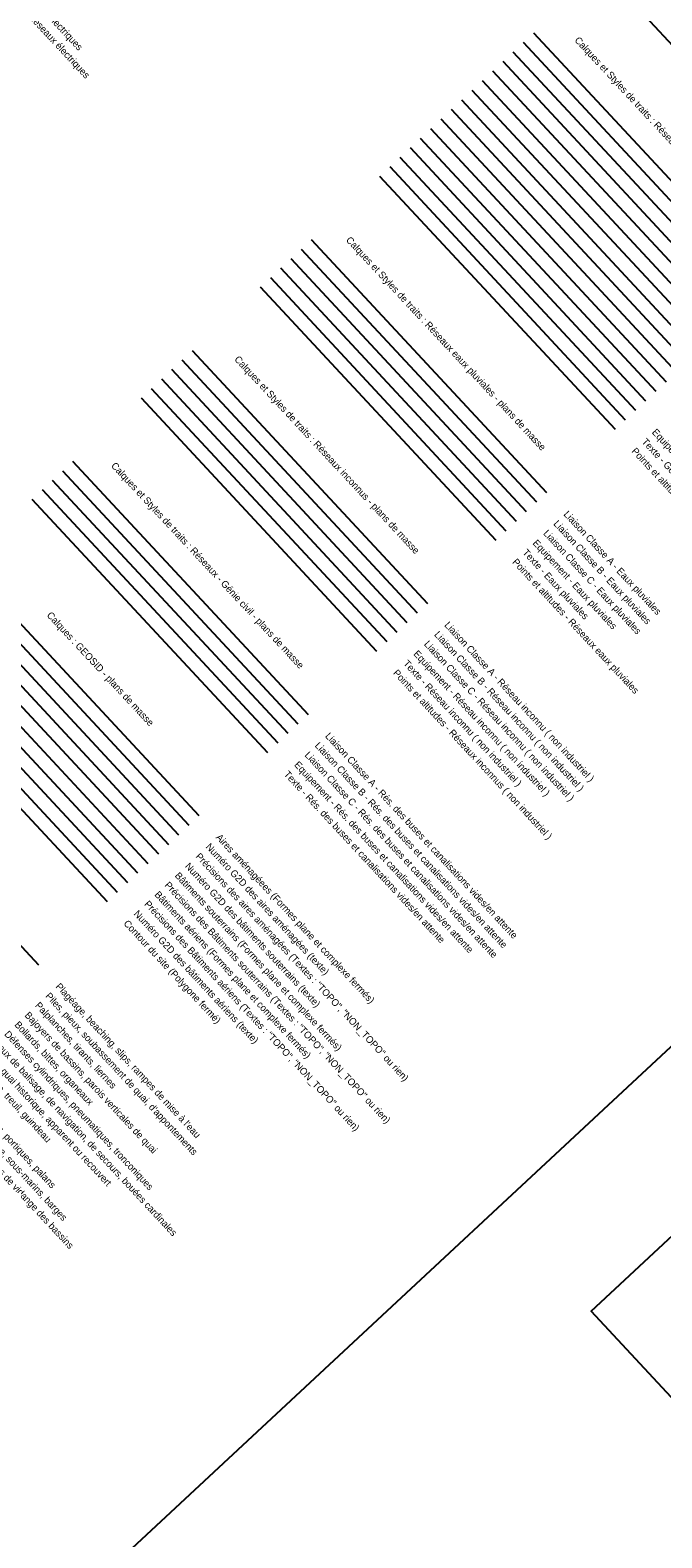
# Model space of a CAD drawing. Extents: x 704383 to 706615, y 7057567 to 7059313.
# Drawn here: x 706453 to 706498.3, y 7057621.5 to 7057729.7 of the extents above; entities that cross this region are included whole.
import ezdxf

# ---------------------------------------------------------------- set-up
doc = ezdxf.new("R2010")
doc.units = 0
for name, color, linetype in [('DH_CADRE -CARTOUCHE', 7, 'Continuous'), ('GEOSID_AIRE_AMENAGEE_NUMERO', 7, 'Continuous'), ('GEOSID_AIRE_AMENAGEE_POLYGONE', 7, 'Continuous'), ('GEOSID_AIRE_AMENAGEE_PRECISION', 7, 'Continuous'), ('GEOSID_BATI_AERIEN _POLYGONE', 7, 'Continuous'), ('GEOSID_BATI_AERIEN_NUMERO', 7, 'Continuous'), ('GEOSID_BATI_AERIEN_PRECISION', 7, 'Continuous'), ('GEOSID_BATI_SOUTERRAIN_NUMERO', 7, 'Continuous'), ('GEOSID_BATI_SOUTERRAIN_POLYGONE', 7, 'Continuous'), ('GEOSID_BATI_SOUTERRAIN_PRECISION', 7, 'Continuous'), ('GEOSID_SITE_POLYGONE', 7, 'Continuous'), ('OM_BAJOYER', 7, 'Continuous'), ('OM_BOLLARDS', 7, 'Continuous'), ('OM_CABESTAN', 7, 'Continuous'), ('OM_DEFENSE D ACCOSTAGE', 7, 'Continuous'), ('OM_EQUIP DE LEVAGE', 7, 'Continuous'), ('OM_GALERIE REFOULEMENT', 7, 'Continuous'), ('OM_NAVIRE', 7, 'Continuous'), ('OM_PAL TIR LIER', 7, 'Continuous'), ('OM_PLAGEAGE', 7, 'Continuous'), ('OM_QUAI', 7, 'Continuous'), ('OM_SIGNAL NAUTIQUE', 7, 'Continuous'), ('OM_SOUBASSEMENT', 7, 'Continuous'), ('R_CF_ALT_POINT', 7, 'Continuous'), ('R_CH_ALT_POINT', 7, 'Continuous'), ('R_CH_GEOTHERMIE_CANALISATION_CL_A', 7, 'Continuous'), ('R_CH_GEOTHERMIE_CANALISATION_CL_B', 7, 'Continuous'), ('R_CH_GEOTHERMIE_CANALISATION_CL_C', 7, 'Continuous'), ('R_CH_GEOTHERMIE_EQUIP', 7, 'Continuous'), ('R_CH_GEOTHERMIE_TEXTE', 7, 'Continuous'), ('R_CH_PRIM_CANALISATION_CL_A', 7, 'Continuous'), ('R_CH_PRIM_CANALISATION_CL_B', 7, 'Continuous'), ('R_CH_PRIM_CANALISATION_CL_C', 7, 'Continuous'), ('R_CH_PRIM_EQUIP', 7, 'Continuous'), ('R_CH_PRIM_TEXTE', 7, 'Continuous'), ('R_CH_SECOND_CANALISATION_CL_A', 7, 'Continuous'), ('R_CH_SECOND_CANALISATION_CL_B', 7, 'Continuous'), ('R_CH_SECOND_CANALISATION_CL_C', 7, 'Continuous'), ('R_CH_SECOND_EQUIP', 7, 'Continuous'), ('R_CH_SECOND_TEXTE', 7, 'Continuous'), ('R_ELEC_ALT_POINT', 7, 'Continuous'), ('R_ELEC_POSTE', 7, 'Continuous'), ('R_GC_BUSES_CANA_CL_A', 7, 'Continuous'), ('R_GC_BUSES_CANA_CL_B', 7, 'Continuous'), ('R_GC_BUSES_CANA_CL_C', 7, 'Continuous'), ('R_GC_BUSES_CANA_EQUIP', 7, 'Continuous'), ('R_GC_BUSES_CANA_TEXTE', 7, 'Continuous'), ('R_INCONNU_ALT_POINT', 7, 'Continuous'), ('R_INCONNU_CANALISATION_CL_A', 7, 'Continuous'), ('R_INCONNU_CANALISATION_CL_B', 7, 'Continuous'), ('R_INCONNU_CANALISATION_CL_C', 7, 'Continuous'), ('R_INCONNU_EQUIP', 7, 'Continuous'), ('R_INCONNU_TEXTE', 7, 'Continuous'), ('R_PLU_ALT_POINT', 7, 'Continuous'), ('R_PLU_CANALISATION_CL_A', 7, 'Continuous'), ('R_PLU_CANALISATION_CL_B', 7, 'Continuous'), ('R_PLU_CANALISATION_CL_C', 7, 'Continuous'), ('R_PLU_EQUIP', 7, 'Continuous'), ('R_PLU_TEXTE', 7, 'Continuous')]:
    doc.layers.add(name, color=color, linetype=linetype)

msp = doc.modelspace()

# ---------------------------------------------------------------- linework, layer by layer
at = {"layer": 'DH_CADRE -CARTOUCHE'}
for points in [[(706481.84, 7057811.55), (706566.98, 7057720.03), (706402.25, 7057566.77), (706317.1, 7057658.29)], [(706573.79, 7057712.71), (706614.66, 7057668.78), (706534.12, 7057593.85), (706493.26, 7057637.78)]]:
    msp.add_lwpolyline(points, close=True, dxfattribs=at)
at = {"layer": 'GEOSID_AIRE_AMENAGEE_NUMERO'}
msp.add_line((706447.47, 7057690.82), (706464.37, 7057672.66), dxfattribs=at)
at = {"layer": 'GEOSID_AIRE_AMENAGEE_POLYGONE'}
msp.add_line((706448.2, 7057691.5), (706465.1, 7057673.34), dxfattribs=at)
at = {"layer": 'GEOSID_AIRE_AMENAGEE_PRECISION'}
msp.add_line((706446.74, 7057690.14), (706463.64, 7057671.97), dxfattribs=at)
at = {"layer": 'GEOSID_BATI_AERIEN _POLYGONE'}
msp.add_line((706443.79, 7057687.4), (706460.69, 7057669.23), dxfattribs=at)
at = {"layer": 'GEOSID_BATI_AERIEN_NUMERO'}
msp.add_line((706442.32, 7057686.03), (706459.23, 7057667.86), dxfattribs=at)
at = {"layer": 'GEOSID_BATI_AERIEN_PRECISION'}
msp.add_line((706443.05, 7057686.72), (706459.96, 7057668.55), dxfattribs=at)
at = {"layer": 'GEOSID_BATI_SOUTERRAIN_NUMERO'}
msp.add_line((706446, 7057689.46), (706462.92, 7057671.28), dxfattribs=at)
at = {"layer": 'GEOSID_BATI_SOUTERRAIN_POLYGONE'}
msp.add_line((706445.27, 7057688.78), (706462.19, 7057670.6), dxfattribs=at)
at = {"layer": 'GEOSID_BATI_SOUTERRAIN_PRECISION'}
msp.add_line((706444.52, 7057688.08), (706461.42, 7057669.91), dxfattribs=at)
at = {"layer": 'GEOSID_SITE_POLYGONE'}
msp.add_line((706441.59, 7057685.35), (706458.5, 7057667.17), dxfattribs=at)
at = {"layer": 'OM_PLAGEAGE'}
msp.add_line((706436.69, 7057680.8), (706453.59, 7057662.63), dxfattribs=at)
at = {"layer": 'R_CF_ALT_POINT'}
msp.add_line((706494.01, 7057734.09), (706510.92, 7057715.91), dxfattribs=at)
at = {"layer": 'R_CH_ALT_POINT'}
msp.add_line((706478.06, 7057719.25), (706494.97, 7057701.07), dxfattribs=at)
at = {"layer": 'R_CH_GEOTHERMIE_CANALISATION_CL_A'}
msp.add_line((706481.72, 7057722.66), (706498.63, 7057704.49), dxfattribs=at)
at = {"layer": 'R_CH_GEOTHERMIE_CANALISATION_CL_B'}
msp.add_line((706480.99, 7057721.98), (706497.89, 7057703.8), dxfattribs=at)
at = {"layer": 'R_CH_GEOTHERMIE_CANALISATION_CL_C'}
msp.add_line((706480.25, 7057721.3), (706497.16, 7057703.12), dxfattribs=at)
at = {"layer": 'R_CH_GEOTHERMIE_EQUIP'}
msp.add_line((706479.52, 7057720.61), (706496.44, 7057702.44), dxfattribs=at)
at = {"layer": 'R_CH_GEOTHERMIE_TEXTE'}
msp.add_line((706478.79, 7057719.93), (706495.7, 7057701.75), dxfattribs=at)
at = {"layer": 'R_CH_PRIM_CANALISATION_CL_A'}
msp.add_line((706489.11, 7057729.53), (706506.01, 7057711.36), dxfattribs=at)
at = {"layer": 'R_CH_PRIM_CANALISATION_CL_B'}
msp.add_line((706488.38, 7057728.85), (706505.28, 7057710.68), dxfattribs=at)
at = {"layer": 'R_CH_PRIM_CANALISATION_CL_C'}
msp.add_line((706487.64, 7057728.17), (706504.55, 7057710), dxfattribs=at)
at = {"layer": 'R_CH_PRIM_EQUIP'}
msp.add_line((706486.91, 7057727.49), (706503.82, 7057709.31), dxfattribs=at)
at = {"layer": 'R_CH_PRIM_TEXTE'}
msp.add_line((706486.18, 7057726.81), (706503.09, 7057708.63), dxfattribs=at)
at = {"layer": 'R_CH_SECOND_CANALISATION_CL_A'}
msp.add_line((706485.43, 7057726.11), (706502.33, 7057707.93), dxfattribs=at)
at = {"layer": 'R_CH_SECOND_CANALISATION_CL_B'}
msp.add_line((706484.69, 7057725.42), (706501.6, 7057707.25), dxfattribs=at)
at = {"layer": 'R_CH_SECOND_CANALISATION_CL_C'}
msp.add_line((706483.94, 7057724.72), (706500.84, 7057706.55), dxfattribs=at)
at = {"layer": 'R_CH_SECOND_EQUIP'}
msp.add_line((706483.21, 7057724.04), (706500.12, 7057705.86), dxfattribs=at)
at = {"layer": 'R_CH_SECOND_TEXTE'}
msp.add_line((706482.47, 7057723.36), (706499.39, 7057705.18), dxfattribs=at)
at = {"layer": 'R_GC_BUSES_CANA_CL_A'}
msp.add_line((706456.03, 7057698.78), (706472.94, 7057680.61), dxfattribs=at)
at = {"layer": 'R_GC_BUSES_CANA_CL_B'}
msp.add_line((706455.3, 7057698.1), (706472.2, 7057679.93), dxfattribs=at)
at = {"layer": 'R_GC_BUSES_CANA_CL_C'}
msp.add_line((706454.57, 7057697.42), (706471.47, 7057679.25), dxfattribs=at)
at = {"layer": 'R_GC_BUSES_CANA_EQUIP'}
msp.add_line((706453.84, 7057696.74), (706470.75, 7057678.56), dxfattribs=at)
at = {"layer": 'R_GC_BUSES_CANA_TEXTE'}
msp.add_line((706453.1, 7057696.06), (706470.02, 7057677.88), dxfattribs=at)
at = {"layer": 'R_INCONNU_ALT_POINT'}
msp.add_line((706460.94, 7057703.33), (706477.85, 7057685.15), dxfattribs=at)
at = {"layer": 'R_INCONNU_CANALISATION_CL_A'}
msp.add_line((706464.6, 7057706.74), (706481.5, 7057688.57), dxfattribs=at)
at = {"layer": 'R_INCONNU_CANALISATION_CL_B'}
msp.add_line((706463.86, 7057706.06), (706480.77, 7057687.89), dxfattribs=at)
at = {"layer": 'R_INCONNU_CANALISATION_CL_C'}
msp.add_line((706463.13, 7057705.38), (706480.03, 7057687.21), dxfattribs=at)
at = {"layer": 'R_INCONNU_EQUIP'}
msp.add_line((706462.4, 7057704.69), (706479.31, 7057686.52), dxfattribs=at)
at = {"layer": 'R_INCONNU_TEXTE'}
msp.add_line((706461.67, 7057704.01), (706478.58, 7057685.83), dxfattribs=at)
at = {"layer": 'R_PLU_ALT_POINT'}
msp.add_line((706469.5, 7057711.29), (706486.41, 7057693.11), dxfattribs=at)
at = {"layer": 'R_PLU_CANALISATION_CL_A'}
msp.add_line((706473.16, 7057714.7), (706490.05, 7057696.54), dxfattribs=at)
at = {"layer": 'R_PLU_CANALISATION_CL_B'}
msp.add_line((706472.43, 7057714.01), (706489.32, 7057695.86), dxfattribs=at)
at = {"layer": 'R_PLU_CANALISATION_CL_C'}
msp.add_line((706471.7, 7057713.33), (706488.59, 7057695.18), dxfattribs=at)
at = {"layer": 'R_PLU_EQUIP'}
msp.add_line((706470.96, 7057712.65), (706487.88, 7057694.47), dxfattribs=at)
at = {"layer": 'R_PLU_TEXTE'}
msp.add_line((706470.23, 7057711.97), (706487.14, 7057693.79), dxfattribs=at)

# ---------------------------------------------------------------- texts
at = {"layer": 'DH_CADRE -CARTOUCHE'}
for s, p in [(' Calques et Styles de traits : Réseaux chauffage - plans de masse', (706491.9, 7057729.1)), (' Calques et Styles de traits : Réseaux eaux pluviales - plans de masse', (706475.49, 7057714.76)), (' Calques et Styles de traits : Réseaux inconnus - plans de masse', (706467.48, 7057706.2)), (' Calques et Styles de traits : Réseaux - Génie civil - plans de masse', (706458.63, 7057698.56)), (' Calques : GEOSID - plans de masse', (706454.01, 7057687.83))]:
    msp.add_text(s, height=0.5, rotation=312.9332, dxfattribs=at).set_placement(p)
at = {"layer": 'GEOSID_AIRE_AMENAGEE_NUMERO'}
msp.add_text('Numéro G2D des aires aménagées (texte)', height=0.5, rotation=312.9332, dxfattribs=at).set_placement((706465.55, 7057671.07))
at = {"layer": 'GEOSID_AIRE_AMENAGEE_POLYGONE'}
msp.add_text('Aires aménagéees (Formes plane et complexe fermés)', height=0.5, rotation=312.9332, dxfattribs=at).set_placement((706466.28, 7057671.75))
at = {"layer": 'GEOSID_AIRE_AMENAGEE_PRECISION'}
msp.add_text('Précisions des aires aménagées (Textes : "TOPO", "NON_TOPO" ou rien)', height=0.5, rotation=312.9332, dxfattribs=at).set_placement((706464.82, 7057670.38))
at = {"layer": 'GEOSID_BATI_AERIEN _POLYGONE'}
msp.add_text('Bâtiments aériens (Formes plane et complexe fermés)', height=0.5, rotation=312.9332, dxfattribs=at).set_placement((706461.87, 7057667.64))
at = {"layer": 'GEOSID_BATI_AERIEN_NUMERO'}
msp.add_text('Numéro G2D des bâtiments aériens (texte)', height=0.5, rotation=312.9332, dxfattribs=at).set_placement((706460.38, 7057666.26))
at = {"layer": 'GEOSID_BATI_AERIEN_PRECISION'}
msp.add_text('Précisions des Bâtiments aériens (Textes : "TOPO", "NON_TOPO" ou rien)', height=0.5, rotation=312.9332, dxfattribs=at).set_placement((706461.14, 7057666.96))
at = {"layer": 'GEOSID_BATI_SOUTERRAIN_NUMERO'}
msp.add_text('Numéro G2D des bâtiments souterrains (texte)', height=0.5, rotation=312.9332, dxfattribs=at).set_placement((706464.06, 7057669.68))
at = {"layer": 'GEOSID_BATI_SOUTERRAIN_POLYGONE'}
msp.add_text('Bâtiments souterrains (Formes plane et complexe fermés)', height=0.5, rotation=312.9332, dxfattribs=at).set_placement((706463.33, 7057669))
at = {"layer": 'GEOSID_BATI_SOUTERRAIN_PRECISION'}
msp.add_text('Précisions des Bâtiments souterrains (Textes : "TOPO", "NON_TOPO" ou rien)', height=0.5, rotation=312.9332, dxfattribs=at).set_placement((706462.6, 7057668.32))
at = {"layer": 'GEOSID_SITE_POLYGONE'}
msp.add_text('Contour du site (Polygone fermé)', height=0.5, rotation=312.9332, dxfattribs=at).set_placement((706459.65, 7057665.57))
at = {"layer": 'OM_BAJOYER'}
msp.add_text('Bajoyers de bassins, parois verticales de quai', height=0.5, rotation=312.9332, dxfattribs=at).set_placement((706452.55, 7057658.98))
at = {"layer": 'OM_BOLLARDS'}
msp.add_text('Bollards, bittes, organeaux', height=0.5, rotation=312.9332, dxfattribs=at).set_placement((706451.82, 7057658.3))
at = {"layer": 'OM_CABESTAN'}
msp.add_text('Cabestan, treuil, guindeau', height=0.5, rotation=312.9332, dxfattribs=at).set_placement((706448.87, 7057655.55))
at = {"layer": 'OM_DEFENSE D ACCOSTAGE'}
msp.add_text('Défenses cylindriques, pneumatiques, tronconiques', height=0.5, rotation=312.9332, dxfattribs=at).set_placement((706451.09, 7057657.62))
at = {"layer": 'OM_EQUIP DE LEVAGE'}
msp.add_text('Grues portuaires, portiques, palans', height=0.5, rotation=312.9332, dxfattribs=at).set_placement((706447.4, 7057654.19))
at = {"layer": 'OM_GALERIE REFOULEMENT'}
msp.add_text('Equipement et systèmes de vidange des bassins', height=0.5, rotation=312.9332, dxfattribs=at).set_placement((706445.92, 7057652.81))
at = {"layer": 'OM_NAVIRE'}
msp.add_text('Bâtiments de surface, sous-marins, barges', height=0.5, rotation=312.9332, dxfattribs=at).set_placement((706446.67, 7057653.51))
at = {"layer": 'OM_PAL TIR LIER'}
msp.add_text('Palplanches, tirants, liernes', height=0.5, rotation=312.9332, dxfattribs=at).set_placement((706453.3, 7057659.68))
at = {"layer": 'OM_PLAGEAGE'}
msp.add_text("Plagéage, beaching, slips, rampes de mise à l'eau", height=0.5, rotation=312.9332, dxfattribs=at).set_placement((706454.77, 7057661.04))
at = {"layer": 'OM_QUAI'}
msp.add_text('Quai, quai historique, apparent ou recouvert', height=0.5, rotation=312.9332, dxfattribs=at).set_placement((706449.62, 7057656.25))
at = {"layer": 'OM_SIGNAL NAUTIQUE'}
msp.add_text('Feux de balisage, de navigation, de secours, bouées cardinales', height=0.5, rotation=312.9332, dxfattribs=at).set_placement((706450.35, 7057656.94))
at = {"layer": 'OM_SOUBASSEMENT'}
msp.add_text("Piles, pieux, soubassement de quai, d'appontements", height=0.5, rotation=312.9332, dxfattribs=at).set_placement((706454.04, 7057660.36))
at = {"layer": 'R_CH_ALT_POINT'}
msp.add_text('Points et altitudes - Réseaux chauffage', height=0.5, rotation=312.9332, dxfattribs=at).set_placement((706496.12, 7057699.47))
at = {"layer": 'R_CH_GEOTHERMIE_EQUIP'}
msp.add_text('Equipement - Géothermie', height=0.5, rotation=312.9332, dxfattribs=at).set_placement((706497.58, 7057700.83))
at = {"layer": 'R_CH_GEOTHERMIE_TEXTE'}
msp.add_text('Texte - Géothermie', height=0.5, rotation=312.9332, dxfattribs=at).set_placement((706496.85, 7057700.15))
at = {"layer": 'R_ELEC_ALT_POINT'}
msp.add_text('Points et altitudes - Réseaux électriques', height=0.5, rotation=312.9332, dxfattribs=at).set_placement((706448.32, 7057736.95))
at = {"layer": 'R_ELEC_POSTE'}
msp.add_text('Poste de transformation - Réseaux électriques', height=0.5, rotation=312.9332, dxfattribs=at).set_placement((706447.59, 7057736.27))
at = {"layer": 'R_GC_BUSES_CANA_CL_A'}
msp.add_text('Liaison Classe A - Rés. des buses et canalisations vides/en attente', height=0.5, rotation=312.9332, dxfattribs=at).set_placement((706474.12, 7057679.02))
at = {"layer": 'R_GC_BUSES_CANA_CL_B'}
msp.add_text('Liaison Classe B - Rés. des buses et canalisations vides/en attente', height=0.5, rotation=312.9332, dxfattribs=at).set_placement((706473.38, 7057678.34))
at = {"layer": 'R_GC_BUSES_CANA_CL_C'}
msp.add_text('Liaison Classe C - Rés. des buses et canalisations vides/en attente', height=0.5, rotation=312.9332, dxfattribs=at).set_placement((706472.65, 7057677.66))
at = {"layer": 'R_GC_BUSES_CANA_EQUIP'}
msp.add_text('Equipement - Rés. des buses et canalisations vides/en attente', height=0.5, rotation=312.9332, dxfattribs=at).set_placement((706471.9, 7057676.96))
at = {"layer": 'R_GC_BUSES_CANA_TEXTE'}
msp.add_text('Texte - Rés. des buses et canalisations vides/en attente', height=0.5, rotation=312.9332, dxfattribs=at).set_placement((706471.16, 7057676.28))
at = {"layer": 'R_INCONNU_ALT_POINT'}
msp.add_text('Points et altitudes - Réseaux inconnus ( non industriel )', height=0.5, rotation=312.9332, dxfattribs=at).set_placement((706479, 7057683.55))
at = {"layer": 'R_INCONNU_CANALISATION_CL_A'}
msp.add_text('Liaison Classe A - Réseau inconnu ( non industriel )', height=0.5, rotation=312.9332, dxfattribs=at).set_placement((706482.68, 7057686.98))
at = {"layer": 'R_INCONNU_CANALISATION_CL_B'}
msp.add_text('Liaison Classe B - Réseau inconnu ( non industriel )', height=0.5, rotation=312.9332, dxfattribs=at).set_placement((706481.95, 7057686.3))
at = {"layer": 'R_INCONNU_CANALISATION_CL_C'}
msp.add_text('Liaison Classe C - Réseau inconnu ( non industriel )', height=0.5, rotation=312.9332, dxfattribs=at).set_placement((706481.22, 7057685.62))
at = {"layer": 'R_INCONNU_EQUIP'}
msp.add_text('Equipement - Réseau inconnu ( non industriel )', height=0.5, rotation=312.9332, dxfattribs=at).set_placement((706480.46, 7057684.92))
at = {"layer": 'R_INCONNU_TEXTE'}
msp.add_text('Texte - Réseau inconnu ( non industriel )', height=0.5, rotation=312.9332, dxfattribs=at).set_placement((706479.73, 7057684.23))
at = {"layer": 'R_PLU_ALT_POINT'}
msp.add_text('Points et altitudes - Réseaux eaux pluviales', height=0.5, rotation=312.9332, dxfattribs=at).set_placement((706487.56, 7057691.51))
at = {"layer": 'R_PLU_CANALISATION_CL_A'}
msp.add_text('Liaison Classe A - Eaux pluviales', height=0.5, rotation=312.9332, dxfattribs=at).set_placement((706491.24, 7057694.94))
at = {"layer": 'R_PLU_CANALISATION_CL_B'}
msp.add_text('Liaison Classe B - Eaux pluviales', height=0.5, rotation=312.9332, dxfattribs=at).set_placement((706490.51, 7057694.26))
at = {"layer": 'R_PLU_CANALISATION_CL_C'}
msp.add_text('Liaison Classe C - Eaux pluviales', height=0.5, rotation=312.9332, dxfattribs=at).set_placement((706489.78, 7057693.57))
at = {"layer": 'R_PLU_EQUIP'}
msp.add_text('Equipement - Eaux pluviales', height=0.5, rotation=312.9332, dxfattribs=at).set_placement((706489.02, 7057692.87))
at = {"layer": 'R_PLU_TEXTE'}
msp.add_text('Texte - Eaux pluviales', height=0.5, rotation=312.9332, dxfattribs=at).set_placement((706488.29, 7057692.19))

doc.saveas('drawing.dxf')
